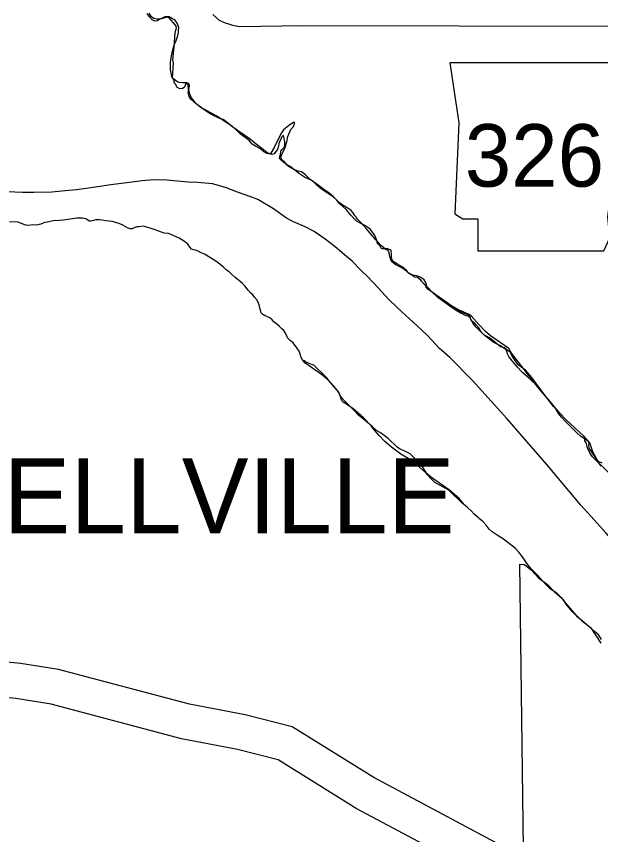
# Model space of a CAD drawing. Extents: x 1374139 to 1377472, y 1168351 to 1170484.
# Drawn here: x 1374423.4 to 1374472.8, y 1169981.2 to 1170050.3 of the extents above; entities that cross this region are included whole.
import ezdxf

# ---------------------------------------------------------------- set-up
doc = ezdxf.new("R2010")
doc.units = 0
doc.layers.add('Default', color=7, linetype='Continuous')

msp = doc.modelspace()

# ---------------------------------------------------------------- linework, layer by layer
at = {"layer": 'Default'}
for points in [[(1374440.905, 1170041.619), (1374440.594, 1170041.724), (1374439.799, 1170042.112), (1374439.284, 1170042.434), (1374438.88, 1170042.738), (1374438.555, 1170043.033), (1374438.229, 1170043.448), (1374438.084, 1170043.756), (1374438.02, 1170044.015), (1374437.967, 1170044.194), (1374437.955, 1170044.294), (1374437.932, 1170044.474), (1374437.921, 1170044.584), (1374437.889, 1170044.654), (1374437.829, 1170044.713), (1374437.748, 1170044.731), (1374437.479, 1170044.717), (1374437.159, 1170044.742), (1374436.988, 1170044.839), (1374436.735, 1170045.025), (1374436.562, 1170045.213), (1374436.529, 1170045.412), (1374436.452, 1170045.842), (1374436.432, 1170046.442), (1374436.533, 1170047.014), (1374436.644, 1170047.517), (1374436.757, 1170047.929), (1374436.882, 1170048.221), (1374437.025, 1170048.624), (1374437.119, 1170048.986), (1374437.127, 1170049.146), (1374437.132, 1170049.417), (1374437.007, 1170049.765), (1374436.813, 1170050.042), (1374436.621, 1170050.149), (1374436.319, 1170050.314), (1374436.279, 1170050.304), (1374436.149, 1170050.302), (1374435.959, 1170050.299), (1374435.721, 1170050.195), (1374435.454, 1170050.04), (1374435.306, 1170049.958), (1374435.116, 1170049.944), (1374434.895, 1170050.041), (1374434.661, 1170050.307), (1374434.467, 1170050.585)], [(1374440.905, 1170041.619), (1374440.594, 1170041.724), (1374439.799, 1170042.112), (1374439.284, 1170042.434), (1374438.88, 1170042.738), (1374438.555, 1170043.033), (1374438.229, 1170043.448), (1374438.084, 1170043.756), (1374438.02, 1170044.015), (1374437.967, 1170044.194), (1374437.955, 1170044.294), (1374437.932, 1170044.474), (1374437.921, 1170044.584), (1374437.889, 1170044.654), (1374437.829, 1170044.713), (1374437.748, 1170044.731), (1374437.479, 1170044.717), (1374437.159, 1170044.742), (1374436.988, 1170044.839), (1374436.735, 1170045.025), (1374436.562, 1170045.213), (1374436.529, 1170045.412), (1374436.452, 1170045.842), (1374436.432, 1170046.442), (1374436.533, 1170047.014), (1374436.644, 1170047.517), (1374436.757, 1170047.929), (1374436.882, 1170048.221), (1374437.025, 1170048.624), (1374437.119, 1170048.986), (1374437.127, 1170049.146), (1374437.132, 1170049.417), (1374437.007, 1170049.765), (1374436.813, 1170050.042), (1374436.621, 1170050.149), (1374436.319, 1170050.314), (1374436.279, 1170050.304), (1374436.149, 1170050.302), (1374435.959, 1170050.299), (1374435.721, 1170050.195), (1374435.454, 1170050.04), (1374435.306, 1170049.958), (1374435.116, 1170049.944), (1374434.895, 1170050.041), (1374434.661, 1170050.307), (1374434.467, 1170050.585)], [(1374437.224, 1170044.232), (1374437.04, 1170044.318), (1374436.943, 1170044.437), (1374436.878, 1170044.578), (1374436.759, 1170044.719), (1374436.737, 1170044.892), (1374436.705, 1170045.044), (1374436.618, 1170045.185), (1374436.651, 1170045.499), (1374436.662, 1170046.008), (1374436.694, 1170046.43), (1374436.64, 1170046.679), (1374436.781, 1170048.033), (1374436.802, 1170048.672), (1374436.856, 1170049.106), (1374436.943, 1170049.365), (1374436.911, 1170049.506), (1374436.856, 1170049.615), (1374436.326, 1170050.221), (1374436.164, 1170050.264), (1374435.947, 1170050.232), (1374435.558, 1170050.113), (1374435.309, 1170050.113), (1374434.995, 1170050.178), (1374434.811, 1170050.34), (1374434.627, 1170050.611)], [(1374474.033, 1170049.479), (1374447.66, 1170049.54), (1374442.267, 1170049.473), (1374441.72, 1170049.585), (1374441.364, 1170049.672), (1374441.081, 1170049.783), (1374440.571, 1170049.999), (1374440.026, 1170050.503)], [(1374453.964, 1170031.153), (1374453.89, 1170031.391), (1374453.81, 1170031.61), (1374453.696, 1170031.882), (1374453.333, 1170032.348), (1374453.139, 1170032.503), (1374452.877, 1170032.651), (1374452.528, 1170032.819), (1374452.159, 1170033.064), (1374451.684, 1170033.542), (1374451.316, 1170033.997), (1374450.775, 1170034.506), (1374450.515, 1170034.809), (1374450.201, 1170035.09), (1374449.898, 1170035.296), (1374449.465, 1170035.578), (1374449.086, 1170035.849), (1374448.816, 1170036.087), (1374448.578, 1170036.325), (1374448.253, 1170036.553), (1374447.874, 1170036.953), (1374447.528, 1170037.192), (1374447.236, 1170037.267), (1374447.008, 1170037.354), (1374446.565, 1170037.571), (1374446.337, 1170037.744), (1374446.078, 1170038.058), (1374445.829, 1170038.275), (1374445.785, 1170038.437), (1374445.872, 1170038.675), (1374446.121, 1170039.195), (1374446.283, 1170039.726), (1374446.37, 1170040.181), (1374446.63, 1170040.777), (1374446.846, 1170041.037), (1374446.943, 1170041.286), (1374446.922, 1170041.394), (1374446.857, 1170041.361), (1374446.716, 1170041.275), (1374446.424, 1170041.08), (1374445.991, 1170040.755), (1374445.818, 1170040.495), (1374445.591, 1170040.083), (1374445.201, 1170039.271), (1374444.93, 1170038.773), (1374444.811, 1170038.73), (1374444.595, 1170038.751), (1374444.324, 1170038.881), (1374444.043, 1170039.152), (1374443.632, 1170039.369), (1374443.361, 1170039.531), (1374443.09, 1170039.845), (1374442.744, 1170040.116), (1374442.355, 1170040.398), (1374441.943, 1170040.82), (1374441.38, 1170041.221), (1374440.309, 1170041.946), (1374439.043, 1170042.64), (1374438.621, 1170042.964), (1374438.166, 1170043.344), (1374438.025, 1170043.571), (1374437.928, 1170043.918), (1374437.982, 1170044.123), (1374438.036, 1170044.459), (1374437.993, 1170044.632), (1374437.917, 1170044.687), (1374437.831, 1170044.676), (1374437.722, 1170044.578), (1374437.657, 1170044.448), (1374437.592, 1170044.318), (1374437.441, 1170044.253), (1374437.224, 1170044.232)], [(1374465.051, 1170022.251), (1374463.524, 1170023.323), (1374463.101, 1170023.69), (1374462.529, 1170024.289), (1374461.884, 1170025.013), (1374461.717, 1170025.13), (1374460.869, 1170025.503), (1374460.117, 1170025.916), (1374459.645, 1170026.157), (1374459.048, 1170026.578), (1374458.541, 1170027.05), (1374458.276, 1170027.366), (1374458.114, 1170027.504), (1374457.902, 1170027.69), (1374457.677, 1170027.967), (1374457.616, 1170028.046), (1374457.515, 1170028.135), (1374457.343, 1170028.262), (1374457.113, 1170028.308), (1374457.022, 1170028.357), (1374456.547, 1170028.669), (1374456.395, 1170028.807), (1374456.021, 1170029.071), (1374455.447, 1170029.372), (1374455.234, 1170029.569), (1374455.091, 1170029.757), (1374455.007, 1170030.056), (1374454.964, 1170030.225), (1374454.942, 1170030.345), (1374454.88, 1170030.484), (1374454.819, 1170030.553), (1374454.688, 1170030.621), (1374454.667, 1170030.641), (1374454.647, 1170030.641), (1374454.313, 1170030.926), (1374453.805, 1170031.438), (1374453.327, 1170032.001), (1374453.001, 1170032.396), (1374452.553, 1170032.909), (1374452.319, 1170033.146), (1374452.187, 1170033.324), (1374452.166, 1170033.343), (1374452.065, 1170033.462), (1374452.044, 1170033.502), (1374451.86, 1170033.759), (1374451.727, 1170033.927), (1374451.525, 1170034.074), (1374451.465, 1170034.113), (1374451.041, 1170034.356), (1374450.657, 1170034.65), (1374450.22, 1170035.084), (1374449.856, 1170035.408), (1374449.421, 1170035.721), (1374448.926, 1170036.084), (1374448.34, 1170036.505), (1374447.786, 1170036.746), (1374447.352, 1170037.029), (1374446.563, 1170037.647), (1374446.17, 1170037.891), (1374445.988, 1170038.008), (1374445.846, 1170038.126), (1374445.785, 1170038.205), (1374445.673, 1170038.323), (1374445.68, 1170038.504), (1374445.737, 1170038.665), (1374445.783, 1170038.956), (1374445.881, 1170039.077), (1374446.087, 1170039.291), (1374446.114, 1170039.472), (1374446.1, 1170039.732), (1374446.097, 1170039.872), (1374446.064, 1170040.042), (1374446.023, 1170040.161), (1374445.991, 1170040.231), (1374445.951, 1170040.25), (1374445.882, 1170040.189), (1374445.766, 1170039.987), (1374445.593, 1170039.583), (1374445.566, 1170039.373), (1374445.481, 1170039.101), (1374445.276, 1170038.807), (1374445.197, 1170038.736), (1374445.009, 1170038.653), (1374444.768, 1170038.729), (1374444.455, 1170038.944), (1374443.696, 1170039.552), (1374443.22, 1170039.935), (1374442.725, 1170040.267), (1374442.2, 1170040.629), (1374441.795, 1170040.933), (1374440.905, 1170041.619)], [(1374464.949, 1170021.808), (1374464.907, 1170021.958), (1374464.834, 1170022.147), (1374464.702, 1170022.275), (1374464.288, 1170022.518), (1374463.794, 1170022.781), (1374463.461, 1170023.016), (1374463.077, 1170023.32), (1374462.661, 1170023.703), (1374462.285, 1170024.078), (1374462.03, 1170024.384), (1374461.886, 1170024.692), (1374461.803, 1170024.861), (1374461.621, 1170024.988), (1374461.451, 1170025.035), (1374461.068, 1170025.209), (1374460.685, 1170025.423), (1374460.059, 1170025.833), (1374459.645, 1170026.157), (1374459.048, 1170026.578), (1374458.541, 1170027.05), (1374458.276, 1170027.366), (1374458.114, 1170027.504), (1374457.902, 1170027.69), (1374457.677, 1170027.967), (1374457.616, 1170028.046), (1374457.515, 1170028.135), (1374457.343, 1170028.262), (1374457.113, 1170028.308), (1374457.022, 1170028.357), (1374456.547, 1170028.669), (1374456.395, 1170028.807), (1374456.021, 1170029.071), (1374455.447, 1170029.372), (1374455.234, 1170029.569), (1374455.091, 1170029.757), (1374455.007, 1170030.056), (1374454.964, 1170030.225), (1374454.942, 1170030.345), (1374454.88, 1170030.484), (1374454.819, 1170030.553), (1374454.688, 1170030.621), (1374454.667, 1170030.641), (1374454.647, 1170030.641), (1374454.313, 1170030.926), (1374453.805, 1170031.438), (1374453.327, 1170032.001), (1374453.001, 1170032.396), (1374452.553, 1170032.909), (1374452.319, 1170033.146), (1374452.187, 1170033.324), (1374452.166, 1170033.343), (1374452.065, 1170033.462), (1374452.044, 1170033.502), (1374451.86, 1170033.759), (1374451.727, 1170033.927), (1374451.525, 1170034.074), (1374451.465, 1170034.113), (1374451.041, 1170034.356), (1374450.657, 1170034.65), (1374450.22, 1170035.084), (1374449.856, 1170035.408), (1374449.421, 1170035.721), (1374448.926, 1170036.084), (1374448.34, 1170036.505), (1374447.786, 1170036.746), (1374447.352, 1170037.029), (1374446.563, 1170037.647), (1374446.17, 1170037.891), (1374445.988, 1170038.008), (1374445.846, 1170038.126), (1374445.785, 1170038.205), (1374445.673, 1170038.323), (1374445.68, 1170038.504), (1374445.737, 1170038.665), (1374445.783, 1170038.956), (1374445.881, 1170039.077), (1374446.087, 1170039.291), (1374446.114, 1170039.472), (1374446.1, 1170039.732), (1374446.097, 1170039.872), (1374446.064, 1170040.042), (1374446.023, 1170040.161), (1374445.991, 1170040.231), (1374445.951, 1170040.25), (1374445.882, 1170040.189), (1374445.766, 1170039.987), (1374445.593, 1170039.583), (1374445.566, 1170039.373), (1374445.481, 1170039.101), (1374445.276, 1170038.807), (1374445.197, 1170038.736), (1374445.009, 1170038.653), (1374444.768, 1170038.729), (1374444.455, 1170038.944), (1374443.696, 1170039.552), (1374443.22, 1170039.935), (1374442.725, 1170040.267), (1374442.2, 1170040.629), (1374441.795, 1170040.933), (1374440.905, 1170041.619)], [(1374459.385, 1170022.084), (1374459.199, 1170022.275), (1374458.192, 1170023.35), (1374457.289, 1170024.216), (1374456.388, 1170025.013), (1374455.607, 1170025.731), (1374454.876, 1170026.44), (1374454.022, 1170027.357), (1374453.097, 1170028.353), (1374452.539, 1170028.894), (1374451.807, 1170029.653), (1374451.342, 1170030.046), (1374450.36, 1170030.851), (1374449.53, 1170031.498), (1374448.59, 1170032.164), (1374447.845, 1170032.562), (1374446.849, 1170032.966), (1374446.255, 1170033.277), (1374445.154, 1170034.07), (1374443.832, 1170034.869), (1374443.239, 1170035.09), (1374442.095, 1170035.472), (1374441.079, 1170035.866), (1374439.996, 1170036.188), (1374438.735, 1170036.298), (1374437.946, 1170036.315), (1374436.126, 1170036.486), (1374435.007, 1170036.518), (1374434.029, 1170036.452), (1374432.963, 1170036.294), (1374431.378, 1170036.088), (1374429.894, 1170035.884), (1374428.499, 1170035.671), (1374427.542, 1170035.585), (1374426.395, 1170035.476), (1374424.887, 1170035.452), (1374423.908, 1170035.466), (1374422.629, 1170035.505)], [(1374444.835, 1170024.864), (1374444.583, 1170024.98), (1374444.403, 1170025.048), (1374444.251, 1170025.145), (1374444.099, 1170025.283), (1374444.014, 1170025.592), (1374443.938, 1170025.961), (1374443.762, 1170026.339), (1374443.558, 1170026.606), (1374443.395, 1170026.793), (1374443.243, 1170026.931), (1374443.019, 1170027.197), (1374442.734, 1170027.553), (1374442.531, 1170027.75), (1374442.206, 1170028.045), (1374442.014, 1170028.192), (1374441.903, 1170028.26), (1374441.609, 1170028.536), (1374441.396, 1170028.733), (1374441.184, 1170028.899), (1374440.94, 1170029.116), (1374440.485, 1170029.499), (1374440.273, 1170029.635), (1374439.828, 1170029.939), (1374439.314, 1170030.231), (1374439.042, 1170030.356), (1374438.77, 1170030.502), (1374438.559, 1170030.579), (1374438.389, 1170030.596), (1374438.228, 1170030.673), (1374438.116, 1170030.792), (1374437.912, 1170031.089), (1374437.619, 1170031.314), (1374437.175, 1170031.587), (1374436.672, 1170031.809), (1374436.26, 1170031.973), (1374435.909, 1170032.007), (1374435.598, 1170032.122), (1374435.146, 1170032.295), (1374434.633, 1170032.477), (1374434.132, 1170032.599), (1374433.773, 1170032.563), (1374433.584, 1170032.54), (1374433.425, 1170032.497), (1374433.187, 1170032.393), (1374433.087, 1170032.382), (1374432.997, 1170032.39), (1374432.796, 1170032.467), (1374432.413, 1170032.681), (1374432.111, 1170032.826), (1374431.8, 1170032.921), (1374431.519, 1170033.007), (1374430.979, 1170033.048), (1374430.658, 1170033.113), (1374430.398, 1170033.149), (1374430.128, 1170033.144), (1374429.81, 1170033.059), (1374429.681, 1170033.017), (1374429.581, 1170033.025), (1374429.45, 1170033.103), (1374429.268, 1170033.23), (1374428.997, 1170033.296), (1374428.528, 1170033.278), (1374427.382, 1170033.11), (1374427.033, 1170033.094), (1374426.514, 1170033.055), (1374426.047, 1170032.948), (1374425.808, 1170032.904), (1374425.659, 1170032.861), (1374425.461, 1170032.768), (1374425.331, 1170032.736), (1374425.122, 1170032.692), (1374424.872, 1170032.718), (1374424.633, 1170032.694), (1374424.324, 1170032.669), (1374424.113, 1170032.706), (1374423.902, 1170032.802), (1374423.56, 1170032.937), (1374422.831, 1170032.975)], [(1374444.835, 1170024.864), (1374444.583, 1170024.98), (1374444.403, 1170025.048), (1374444.251, 1170025.145), (1374444.099, 1170025.283), (1374444.014, 1170025.592), (1374443.938, 1170025.961), (1374443.762, 1170026.339), (1374443.558, 1170026.606), (1374443.395, 1170026.793), (1374443.243, 1170026.931), (1374443.019, 1170027.197), (1374442.734, 1170027.553), (1374442.531, 1170027.75), (1374442.206, 1170028.045), (1374442.014, 1170028.192), (1374441.903, 1170028.26), (1374441.609, 1170028.536), (1374441.396, 1170028.733), (1374441.184, 1170028.899), (1374440.94, 1170029.116), (1374440.485, 1170029.499), (1374440.273, 1170029.635), (1374439.828, 1170029.939), (1374439.314, 1170030.231), (1374439.042, 1170030.356), (1374438.77, 1170030.502), (1374438.559, 1170030.579), (1374438.389, 1170030.596), (1374438.228, 1170030.673), (1374438.116, 1170030.792), (1374437.912, 1170031.089), (1374437.619, 1170031.314), (1374437.175, 1170031.587), (1374436.672, 1170031.809), (1374436.26, 1170031.973), (1374435.909, 1170032.007), (1374435.598, 1170032.122), (1374435.146, 1170032.295), (1374434.633, 1170032.477), (1374434.132, 1170032.599), (1374433.773, 1170032.563), (1374433.584, 1170032.54), (1374433.425, 1170032.497), (1374433.187, 1170032.393), (1374433.087, 1170032.382), (1374432.997, 1170032.39), (1374432.796, 1170032.467), (1374432.413, 1170032.681), (1374432.111, 1170032.826), (1374431.8, 1170032.921), (1374431.519, 1170033.007), (1374430.979, 1170033.048), (1374430.658, 1170033.113), (1374430.398, 1170033.149), (1374430.128, 1170033.144), (1374429.81, 1170033.059), (1374429.681, 1170033.017), (1374429.581, 1170033.025), (1374429.45, 1170033.103), (1374429.268, 1170033.23), (1374428.997, 1170033.296), (1374428.528, 1170033.278), (1374427.382, 1170033.11), (1374427.033, 1170033.094), (1374426.514, 1170033.055), (1374426.047, 1170032.948), (1374425.808, 1170032.904), (1374425.659, 1170032.861), (1374425.461, 1170032.768), (1374425.331, 1170032.736), (1374425.122, 1170032.692), (1374424.872, 1170032.718), (1374424.633, 1170032.694), (1374424.324, 1170032.669), (1374424.113, 1170032.706), (1374423.902, 1170032.802), (1374423.56, 1170032.937), (1374422.831, 1170032.975)], [(1374471.901, 1170013.429), (1374471.695, 1170013.916), (1374471.62, 1170014.263), (1374471.533, 1170014.371), (1374471.479, 1170014.469), (1374471.49, 1170014.685), (1374471.407, 1170014.839), (1374469.888, 1170016.252), (1374469.367, 1170016.792), (1374468.849, 1170017.36), (1374467.518, 1170019.093), (1374467.009, 1170019.808), (1374466.479, 1170020.436), (1374465.84, 1170020.88), (1374465.548, 1170021.335), (1374465.342, 1170021.628), (1374465.18, 1170021.953), (1374464.92, 1170022.126), (1374464.682, 1170022.321), (1374464.358, 1170022.397), (1374464.022, 1170022.678), (1374463.438, 1170023.177), (1374462.929, 1170023.447), (1374462.68, 1170023.707), (1374462.518, 1170024.021), (1374462.215, 1170024.357), (1374461.879, 1170024.628), (1374461.771, 1170025.018), (1374461.533, 1170025.148), (1374460.808, 1170025.462), (1374458.199, 1170027.292), (1374458.08, 1170027.455), (1374458.091, 1170027.639), (1374458.026, 1170027.855), (1374457.896, 1170028.061), (1374457.615, 1170028.278), (1374457.42, 1170028.365), (1374457.258, 1170028.408), (1374456.944, 1170028.462), (1374456.598, 1170028.646), (1374456.392, 1170028.863), (1374456.046, 1170029.177), (1374455.634, 1170029.393), (1374455.288, 1170029.61), (1374455.145, 1170029.873), (1374455.139, 1170029.981), (1374455.149, 1170030.078), (1374455.122, 1170030.172), (1374455.105, 1170030.572), (1374454.947, 1170030.646), (1374454.833, 1170030.683), (1374454.692, 1170030.706), (1374454.618, 1170030.696), (1374454.538, 1170030.683), (1374454.367, 1170030.696), (1374454.28, 1170030.73), (1374454.239, 1170030.773), (1374454.206, 1170030.851), (1374454.139, 1170030.962), (1374454.055, 1170031.042), (1374453.964, 1170031.153)], [(1374460.896, 1170009.566), (1374460.056, 1170010.29), (1374458.448, 1170011.41), (1374458.001, 1170011.772), (1374457.252, 1170012.443), (1374456.83, 1170012.79), (1374455.934, 1170013.338), (1374455.127, 1170013.908), (1374454.582, 1170014.398), (1374454.092, 1170014.914), (1374453.544, 1170015.534), (1374453.436, 1170015.693), (1374452.756, 1170016.39), (1374451.855, 1170017.204), (1374451.186, 1170017.631), (1374451.059, 1170017.724), (1374450.972, 1170017.822), (1374450.879, 1170018.006), (1374450.687, 1170018.578), (1374450.072, 1170019.287), (1374449.73, 1170019.646), (1374449.217, 1170020.056), (1374447.811, 1170021.065), (1374447.561, 1170021.382), (1374447.486, 1170021.514), (1374447.422, 1170021.773), (1374447.318, 1170022.032), (1374447.134, 1170022.329), (1374446.807, 1170022.734), (1374446.595, 1170022.911), (1374446.341, 1170023.177), (1374446.299, 1170023.266), (1374446.103, 1170023.634), (1374446.021, 1170023.772), (1374445.859, 1170023.93), (1374445.656, 1170024.127), (1374445.443, 1170024.314), (1374445.19, 1170024.53), (1374445.028, 1170024.687), (1374444.835, 1170024.864)], [(1374472.896, 1169997.666), (1374472.669, 1169998.027), (1374472.507, 1169998.165), (1374472.284, 1169998.361), (1374472.03, 1169998.597), (1374471.828, 1169998.764), (1374471.646, 1169998.892), (1374471.342, 1169999.137), (1374470.987, 1169999.491), (1374470.774, 1169999.668), (1374470.449, 1169999.993), (1374470.154, 1170000.339), (1374469.91, 1170000.635), (1374469.694, 1170001.022), (1374469.45, 1170001.248), (1374469.115, 1170001.573), (1374468.903, 1170001.72), (1374468.6, 1170001.915), (1374468.225, 1170002.29), (1374467.94, 1170002.605), (1374467.513, 1170003.079), (1374467.218, 1170003.384), (1374466.954, 1170003.64), (1374466.69, 1170003.947), (1374466.454, 1170004.313), (1374466.218, 1170004.66), (1374465.913, 1170005.035), (1374465.638, 1170005.341), (1374465.243, 1170005.675), (1374464.859, 1170005.949), (1374464.687, 1170006.076), (1374464.061, 1170006.487), (1374463.648, 1170006.75), (1374463.394, 1170006.986), (1374463.139, 1170007.313), (1374462.854, 1170007.638), (1374462.58, 1170007.874), (1374462.499, 1170007.953), (1374462.297, 1170008.11), (1374462.115, 1170008.257), (1374461.861, 1170008.533), (1374461.566, 1170008.819), (1374461.06, 1170009.251), (1374460.705, 1170009.575), (1374460.39, 1170009.901), (1374459.984, 1170010.285), (1374458.815, 1170010.926), (1374458.45, 1170011.271), (1374458.185, 1170011.587), (1374457.775, 1170012.231), (1374457.541, 1170012.537), (1374457.327, 1170012.754), (1374457.013, 1170013.039), (1374456.728, 1170013.345), (1374456.386, 1170013.54), (1374456.144, 1170013.636), (1374455.863, 1170013.751), (1374455.61, 1170013.927), (1374454.849, 1170014.656), (1374454.404, 1170014.999), (1374454.253, 1170015.097), (1374453.88, 1170015.331), (1374453.525, 1170015.645), (1374453.079, 1170016.049), (1374452.765, 1170016.284), (1374452.371, 1170016.598), (1374451.974, 1170017.032), (1374451.527, 1170017.485), (1374451.152, 1170017.829), (1374450.887, 1170018.155), (1374450.558, 1170018.721), (1374450.283, 1170019.056), (1374449.958, 1170019.422), (1374449.632, 1170019.807), (1374449.246, 1170020.201), (1374448.941, 1170020.486), (1374448.556, 1170020.85), (1374448.466, 1170020.879), (1374448.164, 1170021.004), (1374447.993, 1170021.071), (1374447.872, 1170021.15), (1374447.841, 1170021.199), (1374447.771, 1170021.208), (1374447.701, 1170021.207), (1374447.61, 1170021.295), (1374447.486, 1170021.514), (1374447.422, 1170021.773), (1374447.318, 1170022.032), (1374447.134, 1170022.329), (1374446.807, 1170022.734), (1374446.595, 1170022.911), (1374446.341, 1170023.177), (1374446.299, 1170023.266), (1374446.103, 1170023.634), (1374446.021, 1170023.772), (1374445.859, 1170023.93), (1374445.656, 1170024.127), (1374445.443, 1170024.314), (1374445.19, 1170024.53), (1374445.028, 1170024.687), (1374444.835, 1170024.864)], [(1374479.855, 1169997.951), (1374479.261, 1169998.575), (1374478.589, 1169999.395), (1374477.395, 1170000.917), (1374476.618, 1170002.056), (1374475.53, 1170003.81), (1374474.304, 1170005.492), (1374473.266, 1170006.687), (1374472.025, 1170008.058), (1374471.146, 1170009.008), (1374468.255, 1170012.494), (1374464.906, 1170016.354), (1374461.996, 1170019.548), (1374460.057, 1170021.512), (1374459.385, 1170022.084)], [(1374472.884, 1170012.314), (1374472.714, 1170012.546), (1374472.295, 1170013.259), (1374472.169, 1170013.532), (1374471.918, 1170014.294), (1374471.407, 1170014.839), (1374469.888, 1170016.252), (1374469.367, 1170016.792), (1374467.538, 1170018.97), (1374465.273, 1170021.88), (1374465.051, 1170022.251)], [(1374472.97, 1170012.559), (1374472.759, 1170012.645), (1374472.648, 1170012.723), (1374472.362, 1170013.089), (1374471.994, 1170013.634), (1374471.892, 1170013.772), (1374471.828, 1170013.992), (1374471.836, 1170014.102), (1374471.854, 1170014.262), (1374471.823, 1170014.322), (1374471.761, 1170014.431), (1374471.368, 1170014.675), (1374471.115, 1170014.861), (1374470.861, 1170015.087), (1374470.516, 1170015.432), (1374470.222, 1170015.727), (1374469.826, 1170016.111), (1374469.521, 1170016.447), (1374469.296, 1170016.753), (1374468.999, 1170017.229), (1374468.703, 1170017.605), (1374468.601, 1170017.733), (1374468.347, 1170018.009), (1374468.204, 1170018.187), (1374468.173, 1170018.237), (1374467.766, 1170018.691), (1374467.368, 1170019.215), (1374467.095, 1170019.451), (1374466.953, 1170019.579), (1374466.659, 1170019.844), (1374466.253, 1170020.218), (1374466.132, 1170020.316), (1374465.806, 1170020.681), (1374465.501, 1170021.027), (1374465.195, 1170021.392), (1374465.073, 1170021.58), (1374464.949, 1170021.808)], [(1374474.964, 1170010.353), (1374472.15, 1170013.115), (1374471.901, 1170013.429)], [(1374472.896, 1169997.666), (1374472.669, 1169998.027), (1374472.507, 1169998.165), (1374472.284, 1169998.361), (1374472.03, 1169998.597), (1374471.828, 1169998.764), (1374471.646, 1169998.892), (1374471.342, 1169999.137), (1374470.987, 1169999.491), (1374470.774, 1169999.668), (1374470.449, 1169999.993), (1374470.154, 1170000.339), (1374469.91, 1170000.635), (1374469.694, 1170001.022), (1374469.45, 1170001.248), (1374469.115, 1170001.573), (1374468.903, 1170001.72), (1374468.6, 1170001.915), (1374468.225, 1170002.29), (1374467.94, 1170002.605), (1374467.513, 1170003.079), (1374467.218, 1170003.384), (1374466.954, 1170003.64), (1374466.69, 1170003.947), (1374466.454, 1170004.313), (1374466.218, 1170004.66), (1374465.913, 1170005.035), (1374465.638, 1170005.341), (1374465.243, 1170005.675), (1374464.859, 1170005.949), (1374464.687, 1170006.076), (1374464.061, 1170006.487), (1374463.648, 1170006.75), (1374463.394, 1170006.986), (1374463.139, 1170007.313), (1374462.854, 1170007.638), (1374462.58, 1170007.874), (1374462.499, 1170007.953), (1374462.297, 1170008.11), (1374462.115, 1170008.257), (1374461.861, 1170008.533), (1374461.566, 1170008.819), (1374461.306, 1170009.041), (1374460.896, 1170009.566)], [(1374466.352, 1169975.837), (1374466.327, 1169977.814), (1374465.987, 1170004.018), (1374466.396, 1170004.014)], [(1374466.396, 1170004.014), (1374466.987, 1170003.526), (1374467.563, 1170002.88), (1374468.329, 1170002.305), (1374468.925, 1170001.679), (1374469.48, 1170001.214), (1374469.873, 1170000.709), (1374470.236, 1170000.285), (1374470.791, 1169999.659), (1374472.002, 1169998.65), (1374472.85, 1169997.357)], [(1374466.428, 1169979.175), (1374453.644, 1169985.978), (1374446.739, 1169990.283), (1374442.762, 1169991.294), (1374438.045, 1169992.185), (1374426.956, 1169995.118), (1374423.752, 1169995.637), (1374415.369, 1169996.44), (1374413.731, 1169996.541), (1374411.516, 1169996.794), (1374409.533, 1169997.331)], [(1374464.97, 1169976.552), (1374452.144, 1169983.378), (1374445.548, 1169987.49), (1374442.113, 1169988.364), (1374437.383, 1169989.257), (1374426.331, 1169992.18), (1374423.369, 1169992.66), (1374415.134, 1169993.449), (1374413.469, 1169993.551), (1374410.95, 1169993.839), (1374408.286, 1169994.56), (1374407.991, 1169994.73)]]:
    msp.add_lwpolyline(points, dxfattribs=at)
msp.add_lwpolyline([(1374460.071, 1170046.413), (1374460.833, 1170041.338), (1374460.494, 1170033.64), (1374461.171, 1170033.217), (1374462.44, 1170033.217), (1374462.44, 1170030.51), (1374473.098, 1170030.51), (1374473.606, 1170031.61), (1374473.436, 1170033.387), (1374473.69, 1170035.417), (1374474.621, 1170037.024), (1374475.213, 1170038.208), (1374476.059, 1170039.477), (1374476.566, 1170040.83), (1374476.989, 1170041.93), (1374477.75, 1170042.861), (1374477.92, 1170043.453), (1374477.581, 1170043.876), (1374474.959, 1170043.876), (1374475.551, 1170045.06), (1374475.636, 1170045.821), (1374475.285, 1170046.406)], close=True, dxfattribs=at)

# ---------------------------------------------------------------- texts
for s, height, p in [('326', 5.28, (1374461.337, 1170035.95)), ('RUSSELLVILLE', 6.33599, (1374398.774, 1170006.649))]:
    msp.add_text(s, height=height, dxfattribs=at).set_placement(p)

doc.saveas('drawing.dxf')
